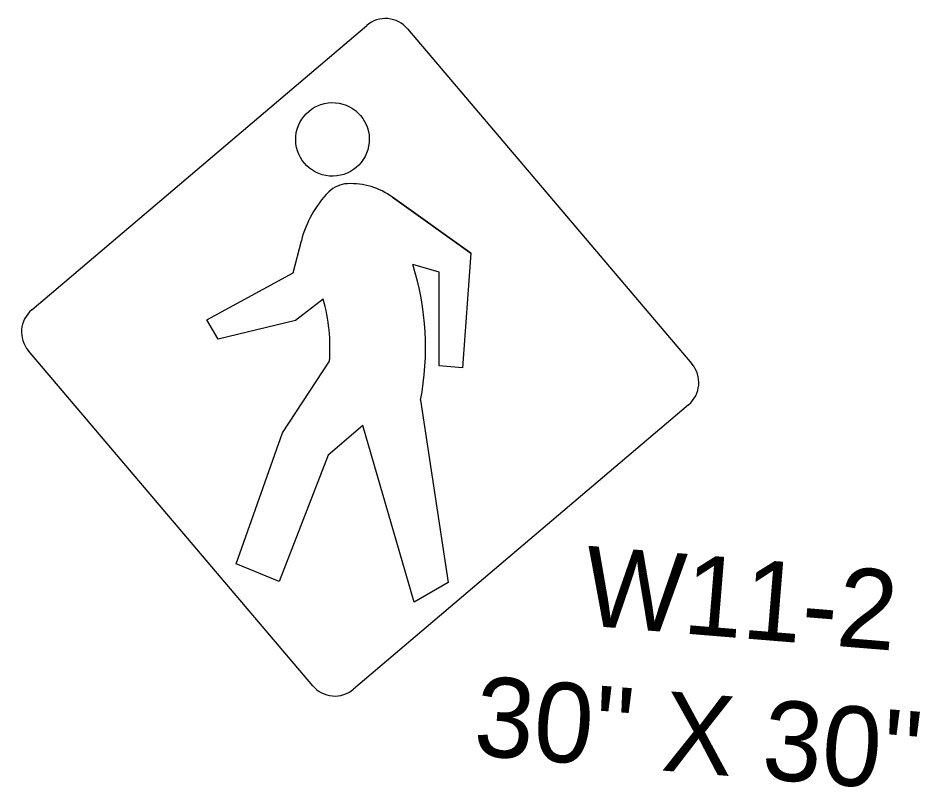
# Model space of a CAD drawing. Extents: x 902965 to 1126554, y 597041 to 686906.
# Drawn here: x 938325.53 to 938359.53, y 683645.73 to 683674.75 of the extents above; entities that cross this region are included whole.
import ezdxf

# ---------------------------------------------------------------- set-up
doc = ezdxf.new("R2010")
doc.units = 0
doc.layers.add('WS W11-2 CELL', color=7, linetype='Continuous')

msp = doc.modelspace()

# ---------------------------------------------------------------- linework, layer by layer
at = {"layer": 'WS W11-2 CELL'}
for p, q in [((938339.647, 683668), (938342.604, 683665.888)), ((938342.604, 683665.888), (938339.647, 683668)), ((938339.647, 683668), (938342.604, 683665.888)), ((938335.909, 683665.147), (938336.213, 683666.356)), ((938342.604, 683665.888), (938342.291, 683661.565)), ((938341.408, 683665.173), (938340.415, 683665.458)), ((938332.644, 683663.371), (938335.909, 683665.147)), ((938341.403, 683661.638), (938341.408, 683665.173)), ((938337.04, 683664.159), (938335.995, 683663.349)), ((938333.072, 683662.645), (938332.644, 683663.371)), ((938335.995, 683663.349), (938333.072, 683662.645)), ((938335.506, 683659.113), (938337.272, 683661.813)), ((938342.291, 683661.565), (938341.403, 683661.638)), ((938340.706, 683660.345), (938341.751, 683653.481)), ((938350.81, 683660.174), (938338.183, 683649.457)), ((938350.81, 683660.174), (938338.183, 683649.457)), ((938338.537, 683659.393), (938337.226, 683658.281)), ((938340.471, 683652.732), (938338.537, 683659.393)), ((938333.761, 683654.175), (938335.506, 683659.113)), ((938337.226, 683658.281), (938335.373, 683653.515)), ((938335.373, 683653.515), (938333.761, 683654.175)), ((938341.751, 683653.481), (938340.471, 683652.732))]:
    msp.add_line(p, q, dxfattribs=at)
for points in [[(938326.05, 683663.752), (938338.677, 683674.47)], [(938340.219, 683674.343), (938350.936, 683661.716)], [(938336.641, 683649.583), (938325.923, 683662.21)]]:
    msp.add_lwpolyline(points, dxfattribs=at)
for centre, major_axis, start_param, end_param in [((938339.385, 683673.636), (0.089, 1.09), 6.283072, 7.068583), ((938339.385, 683673.636), (0.089, 1.09), 5.49756, 6.283072), ((938337.994, 683667.458), (-0.086, -1.046), 3.261682, 4.017186), ((938338.058, 683665.775), (0.223, 2.725), 5.744678, 6.403274), ((938340.113, 683665.375), (-0.328, -4.008), 4.017186, 4.547553), ((938330.531, 683662.331), (0.845, 10.332), 4.60131, 5.100443), ((938330.531, 683662.331), (0.551, 6.738), 4.717416, 5.067864), ((938326.757, 683662.918), (0.089, 1.09), 0.785398, 2.356194), ((938350.102, 683661.008), (0.089, 1.09), 3.926991, 5.497787), ((938337.475, 683650.291), (-0.089, -1.09), 5.497787, 6.283185), ((938337.475, 683650.291), (-0.089, -1.09), 6.283185, 7.068583)]:
    msp.add_ellipse(centre, major_axis=major_axis, ratio=0.999996, start_param=start_param, end_param=end_param, dxfattribs=at)
msp.add_ellipse((938337.387, 683670.176), major_axis=(0.113, 1.382), ratio=0.999996, dxfattribs=at)

# ---------------------------------------------------------------- texts
for s, height, p in [('W11-2', 3, (938346.776, 683651.87)), ("30'' X 30''", 3.00001, (938342.654, 683646.975))]:
    msp.add_text(s, height=height, rotation=355.3221, dxfattribs=at).set_placement(p)

doc.saveas('drawing.dxf')
